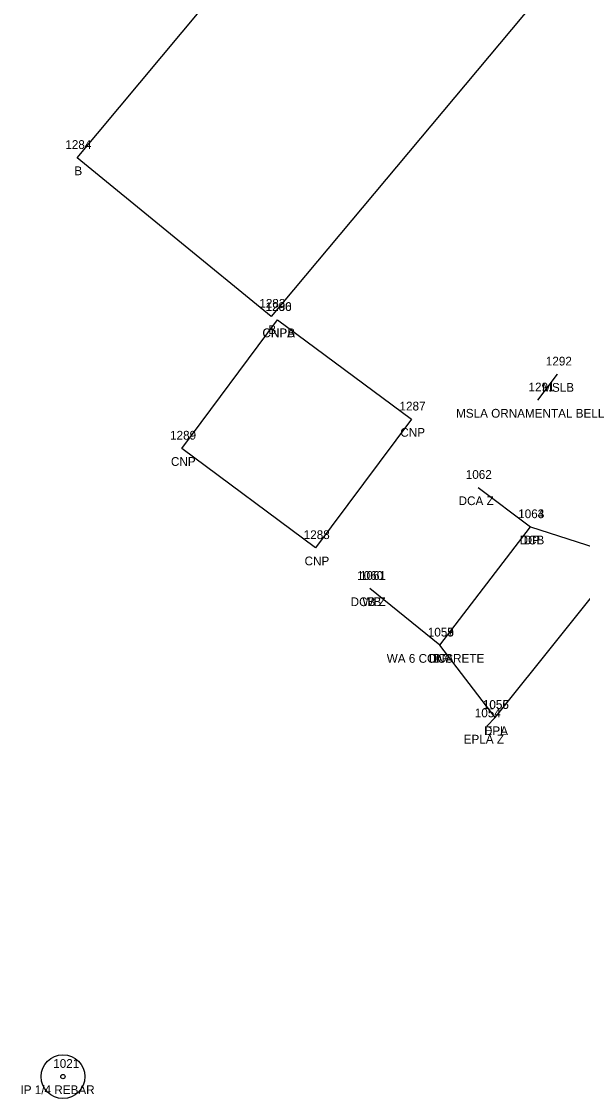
# Model space of a CAD drawing. Extents: x 1812340 to 1815011, y 1177659 to 1180159.
# Drawn here: x 1813776.7 to 1813840.8, y 1178166.1 to 1178289.1 of the extents above; entities that cross this region are included whole.
import ezdxf

# ---------------------------------------------------------------- set-up
doc = ezdxf.new("R2010")
doc.units = 0
for name, color, linetype in [('RD_EX_Bldg', 7, 'Continuous'), ('RD_EX_Bldg_txCode', 7, 'Continuous'), ('RD_EX_BldgApp', 7, 'Continuous'), ('RD_EX_BldgApp_txCode', 7, 'Continuous'), ('RD_EX_Conc', 7, 'Continuous'), ('RD_EX_Conc_txCode', 7, 'Continuous'), ('RD_EX_Driveway', 7, 'Continuous'), ('RD_EX_Driveway_txCode', 7, 'Continuous'), ('RD_EX_DV_Prop_txCode', 7, 'Continuous'), ('RD_EX_DV_PropPin', 7, 'Continuous'), ('RD_EX_Misc', 7, 'Continuous'), ('RD_EX_Misc_txCode', 7, 'Continuous'), ('RD_EX_Road', 7, 'Continuous'), ('RD_EX_Road_txCode', 7, 'Continuous'), ('RD_SMD_Locator', 7, 'Continuous')]:
    doc.layers.add(name, color=color, linetype=linetype)

msp = doc.modelspace()

# ---------------------------------------------------------------- linework, layer by layer
at = {"layer": 'RD_EX_Bldg'}
msp.add_lwpolyline([(1813814.41, 1178311.05), (1813836.59, 1178292.91), (1813805.22, 1178255.39), (1813783.05, 1178273.53), (1813814.41, 1178311.05)], dxfattribs=at)
at = {"layer": 'RD_EX_BldgApp'}
msp.add_line((1813824.51, 1178217.83), (1813816.5, 1178224.3), dxfattribs=at)
msp.add_lwpolyline([(1813805.96, 1178255.02), (1813821.24, 1178243.65), (1813810.29, 1178228.96), (1813795.02, 1178240.32), (1813805.96, 1178255.02)], dxfattribs=at)
at = {"layer": 'RD_EX_Conc'}
for p, q in [((1813828.87, 1178235.84), (1813834.86, 1178231.35)), ((1813824.51, 1178217.83), (1813816.5, 1178224.3))]:
    msp.add_line(p, q, dxfattribs=at)
at = {"layer": 'RD_EX_Driveway'}
msp.add_lwpolyline([(1813830.81, 1178209.56), (1813824.51, 1178217.83), (1813834.86, 1178231.35), (1813845.51, 1178227.94)], dxfattribs=at)
at = {"layer": 'RD_EX_DV_PropPin'}
for radius in [2.5, 0.25]:
    msp.add_circle((1813781.43, 1178168.55), radius, dxfattribs=at)
at = {"layer": 'RD_EX_Misc'}
msp.add_line((1813835.69, 1178245.83), (1813837.95, 1178248.79), dxfattribs=at)
at = {"layer": 'RD_EX_Road'}
msp.add_lwpolyline([(1813829.87, 1178208.6), (1813830.81, 1178209.56), (1813845.51, 1178227.94), (1813874.69, 1178258.74), (1813910.02, 1178295.38), (1813943.63, 1178333.84), (1813974.31, 1178373.09), (1814001.91, 1178410.56), (1814011.9, 1178425.95), (1814015.58, 1178434.3), (1814016.71, 1178442.08), (1814017.03, 1178447.13), (1814015.19, 1178453.67), (1813986.47, 1178480.85), (1813949.15, 1178515.86)], dxfattribs=at)
at = {"layer": 'RD_SMD_Locator'}
for centre in [(1813783.05, 1178273.53), (1813805.22, 1178255.39), (1813805.96, 1178255.02), (1813805.96, 1178255.02), (1813837.95, 1178248.79), (1813835.69, 1178245.83), (1813821.24, 1178243.65), (1813795.02, 1178240.32), (1813828.87, 1178235.84), (1813834.86, 1178231.35), (1813834.86, 1178231.35), (1813810.29, 1178228.96), (1813816.5, 1178224.3), (1813816.5, 1178224.3), (1813824.51, 1178217.83), (1813824.51, 1178217.83), (1813824.51, 1178217.83), (1813830.81, 1178209.56), (1813830.81, 1178209.56), (1813829.87, 1178208.6)]:
    msp.add_circle(centre, 0.001, dxfattribs=at)

# ---------------------------------------------------------------- texts
at = {"layer": 'RD_EX_Bldg_txCode'}
for s, p in [('1284', (1813781.7, 1178274.53)), ('B', (1813782.74, 1178271.53)), ('1283', (1813803.87, 1178256.39)), ('B', (1813804.91, 1178253.39))]:
    msp.add_text(s, height=1, dxfattribs=at).set_placement(p)
at = {"layer": 'RD_EX_BldgApp_txCode'}
for s, p in [('1290', (1813804.58, 1178256.02)), ('1286', (1813804.59, 1178256.02)), ('CNPA', (1813804.22, 1178253.02)), ('CNPB', (1813804.24, 1178253.02)), ('1287', (1813819.89, 1178244.65)), ('CNP', (1813819.98, 1178241.65)), ('1289', (1813793.67, 1178241.32)), ('CNP', (1813793.77, 1178238.32)), ('1288', (1813808.94, 1178229.96)), ('CNP', (1813809.04, 1178226.96)), ('1060', (1813815.05, 1178225.3)), ('WB', (1813815.65, 1178222.3)), ('1059', (1813823.12, 1178218.83)), ('WA 6 CONCRETE', (1813818.43, 1178215.83))]:
    msp.add_text(s, height=1, dxfattribs=at).set_placement(p)
at = {"layer": 'RD_EX_Conc_txCode'}
for s, p in [('1062', (1813827.46, 1178236.84)), ('DCA Z', (1813826.64, 1178233.84)), ('1063', (1813833.45, 1178232.35)), ('DCB', (1813833.61, 1178229.35)), ('1061', (1813815.37, 1178225.3)), ('DCB Z', (1813814.3, 1178222.3)), ('1058', (1813823.12, 1178218.83)), ('DCA', (1813823.24, 1178215.83))]:
    msp.add_text(s, height=1, dxfattribs=at).set_placement(p)
at = {"layer": 'RD_EX_Driveway_txCode'}
for s, p in [('1064', (1813833.45, 1178232.35)), ('DP', (1813834.08, 1178229.35)), ('1057', (1813823.12, 1178218.83)), ('DP', (1813823.73, 1178215.83)), ('1056', (1813829.4, 1178210.56)), ('DPA', (1813829.54, 1178207.56))]:
    msp.add_text(s, height=1, dxfattribs=at).set_placement(p)
at = {"layer": 'RD_EX_DV_Prop_txCode'}
for s, p in [('1021', (1813780.32, 1178169.55)), ('IP 1/4 REBAR', (1813776.58, 1178166.55))]:
    msp.add_text(s, height=1, dxfattribs=at).set_placement(p)
at = {"layer": 'RD_EX_Misc_txCode'}
for s, p in [('1292', (1813836.61, 1178249.79)), ('1291', (1813834.63, 1178246.83)), ('MSLB', (1813836.19, 1178246.79)), ('MSLA ORNAMENTAL BELL', (1813826.35, 1178243.83))]:
    msp.add_text(s, height=1, dxfattribs=at).set_placement(p)
at = {"layer": 'RD_EX_Road_txCode'}
for s, p in [('1055', (1813829.42, 1178210.56)), ('1054', (1813828.49, 1178209.6)), ('EPL', (1813829.6, 1178207.56)), ('EPLA Z', (1813827.22, 1178206.6))]:
    msp.add_text(s, height=1, dxfattribs=at).set_placement(p)

doc.saveas('drawing.dxf')
